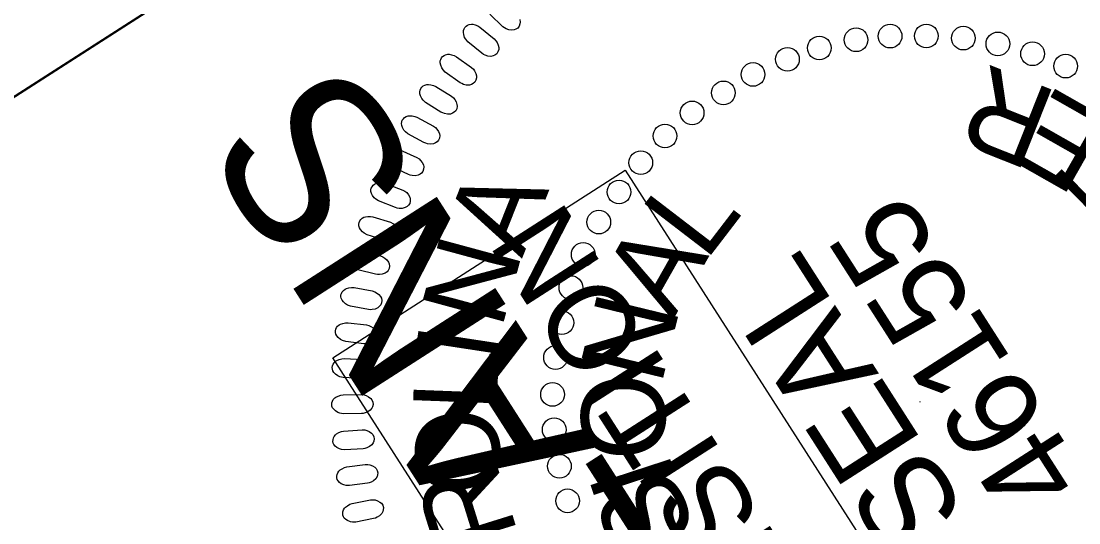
# Model space of a CAD drawing. Extents: x 476646 to 478477, y 498681 to 500689.
# Drawn here: x 476726.9 to 476798.5, y 500100.5 to 500134.4 of the extents above; entities that cross this region are included whole.
import ezdxf

# ---------------------------------------------------------------- set-up
doc = ezdxf.new("R2010")
doc.units = 0
for name, color, linetype in [('Sheet PE Seal Cell', 7, 'Continuous'), ('Sheet Plan CELL', 7, 'Continuous'), ('Sheet Sticker Incomplete CELL', 7, 'Continuous')]:
    doc.layers.add(name, color=color, linetype=linetype)

msp = doc.modelspace()

# ---------------------------------------------------------------- linework, layer by layer
at = {"layer": 'Sheet PE Seal Cell'}
msp.add_line((476787.749, 500108.701), (476787.788, 500108.726), dxfattribs=at)
msp.add_lwpolyline([(476760.68, 500134.556), (476760.706, 500134.379), (476760.698, 500134.253), (476760.635, 500134.098), (476760.548, 500133.975), (476760.417, 500133.893), (476760.309, 500133.85), (476760.149, 500133.825), (476759.944, 500133.852), (476759.767, 500133.926), (476759.651, 500133.992), (476759.546, 500134.069), (476758.649, 500134.905)], dxfattribs=at)
for points in [[(476758.12, 500132.269), (476757.17, 500133.047), (476757.025, 500133.215), (476756.949, 500133.344), (476756.89, 500133.538), (476756.866, 500133.682), (476756.876, 500133.82), (476756.911, 500133.926), (476756.967, 500134.025), (476757.053, 500134.099), (476757.152, 500134.173), (476757.264, 500134.216), (476757.409, 500134.234), (476757.508, 500134.23), (476757.667, 500134.187), (476757.843, 500134.119), (476757.981, 500134.036), (476758.958, 500133.245), (476759.074, 500133.12), (476759.153, 500132.996), (476759.22, 500132.826), (476759.257, 500132.651), (476759.257, 500132.525), (476759.205, 500132.365), (476759.125, 500132.238), (476758.999, 500132.147), (476758.895, 500132.098), (476758.736, 500132.063), (476758.53, 500132.077), (476758.348, 500132.139), (476758.229, 500132.198)], [(476756.644, 500130.284), (476755.648, 500131), (476755.492, 500131.159), (476755.409, 500131.282), (476755.336, 500131.472), (476755.304, 500131.616), (476755.305, 500131.753), (476755.334, 500131.861), (476755.383, 500131.964), (476755.465, 500132.043), (476755.559, 500132.123), (476755.668, 500132.173), (476755.811, 500132.2), (476755.91, 500132.202), (476756.071, 500132.169), (476756.252, 500132.113), (476756.394, 500132.038), (476757.419, 500131.31), (476757.543, 500131.193), (476757.63, 500131.075), (476757.707, 500130.909), (476757.755, 500130.736), (476757.764, 500130.61), (476757.72, 500130.448), (476757.649, 500130.315), (476757.529, 500130.217), (476757.428, 500130.161), (476757.273, 500130.116), (476757.065, 500130.119), (476756.88, 500130.169), (476756.757, 500130.22)], [(476755.353, 500128.292), (476754.315, 500128.945), (476754.149, 500129.093), (476754.058, 500129.211), (476753.974, 500129.397), (476753.934, 500129.538), (476753.925, 500129.675), (476753.947, 500129.785), (476753.99, 500129.891), (476754.067, 500129.975), (476754.156, 500130.06), (476754.262, 500130.117), (476754.402, 500130.152), (476754.501, 500130.161), (476754.664, 500130.138), (476754.848, 500130.093), (476754.995, 500130.027), (476756.063, 500129.365), (476756.194, 500129.255), (476756.289, 500129.143), (476756.376, 500128.983), (476756.435, 500128.813), (476756.451, 500128.689), (476756.418, 500128.524), (476756.355, 500128.387), (476756.242, 500128.281), (476756.144, 500128.219), (476755.992, 500128.164), (476755.784, 500128.154), (476755.597, 500128.192), (476755.471, 500128.236)], [(476754.198, 500126.236), (476753.12, 500126.822), (476752.946, 500126.96), (476752.848, 500127.071), (476752.752, 500127.251), (476752.702, 500127.389), (476752.686, 500127.526), (476752.701, 500127.637), (476752.737, 500127.745), (476752.808, 500127.834), (476752.892, 500127.924), (476752.994, 500127.988), (476753.132, 500128.032), (476753.23, 500128.046), (476753.394, 500128.034), (476753.58, 500128.001), (476753.731, 500127.945), (476754.838, 500127.351), (476754.977, 500127.25), (476755.078, 500127.143), (476755.175, 500126.989), (476755.244, 500126.824), (476755.268, 500126.7), (476755.246, 500126.534), (476755.192, 500126.393), (476755.086, 500126.281), (476754.992, 500126.212), (476754.843, 500126.148), (476754.637, 500126.124), (476754.447, 500126.151), (476754.319, 500126.187)], [(476753.154, 500124.067), (476752.041, 500124.584), (476751.858, 500124.711), (476751.753, 500124.817), (476751.647, 500124.99), (476751.588, 500125.125), (476751.563, 500125.26), (476751.571, 500125.372), (476751.6, 500125.482), (476751.666, 500125.575), (476751.744, 500125.671), (476751.842, 500125.74), (476751.977, 500125.793), (476752.074, 500125.814), (476752.239, 500125.812), (476752.426, 500125.79), (476752.58, 500125.744), (476753.723, 500125.221), (476753.867, 500125.129), (476753.974, 500125.029), (476754.081, 500124.88), (476754.161, 500124.72), (476754.192, 500124.598), (476754.181, 500124.431), (476754.135, 500124.287), (476754.036, 500124.168), (476753.947, 500124.094), (476753.802, 500124.021), (476753.599, 500123.984), (476753.407, 500123.999), (476753.277, 500124.026)], [(476752.272, 500121.837), (476751.13, 500122.284), (476750.939, 500122.399), (476750.828, 500122.498), (476750.71, 500122.664), (476750.644, 500122.795), (476750.61, 500122.928), (476750.611, 500123.04), (476750.633, 500123.152), (476750.693, 500123.249), (476750.764, 500123.349), (476750.858, 500123.425), (476750.989, 500123.486), (476751.085, 500123.513), (476751.249, 500123.521), (476751.438, 500123.512), (476751.594, 500123.475), (476752.768, 500123.024), (476752.917, 500122.942), (476753.032, 500122.849), (476753.147, 500122.708), (476753.236, 500122.552), (476753.275, 500122.433), (476753.274, 500122.265), (476753.238, 500122.118), (476753.147, 500121.994), (476753.062, 500121.914), (476752.923, 500121.832), (476752.722, 500121.782), (476752.53, 500121.785), (476752.398, 500121.804)], [(476751.527, 500119.624), (476750.358, 500119.998), (476750.161, 500120.101), (476750.043, 500120.193), (476749.916, 500120.351), (476749.841, 500120.478), (476749.799, 500120.609), (476749.793, 500120.72), (476749.808, 500120.834), (476749.862, 500120.934), (476749.927, 500121.039), (476750.015, 500121.121), (476750.142, 500121.19), (476750.237, 500121.222), (476750.4, 500121.241), (476750.589, 500121.243), (476750.747, 500121.216), (476751.947, 500120.84), (476752.101, 500120.767), (476752.221, 500120.682), (476752.345, 500120.548), (476752.444, 500120.398), (476752.491, 500120.281), (476752.5, 500120.114), (476752.473, 500119.965), (476752.39, 500119.835), (476752.31, 500119.751), (476752.177, 500119.66), (476751.979, 500119.598), (476751.787, 500119.588), (476751.655, 500119.599)], [(476750.927, 500117.325), (476749.738, 500117.624), (476749.534, 500117.714), (476749.411, 500117.799), (476749.274, 500117.949), (476749.192, 500118.07), (476749.142, 500118.198), (476749.128, 500118.31), (476749.136, 500118.423), (476749.184, 500118.527), (476749.242, 500118.636), (476749.325, 500118.723), (476749.447, 500118.8), (476749.54, 500118.838), (476749.701, 500118.867), (476749.889, 500118.881), (476750.05, 500118.864), (476751.27, 500118.564), (476751.429, 500118.501), (476751.554, 500118.423), (476751.686, 500118.298), (476751.794, 500118.155), (476751.848, 500118.041), (476751.868, 500117.874), (476751.851, 500117.724), (476751.776, 500117.589), (476751.702, 500117.5), (476751.574, 500117.401), (476751.38, 500117.326), (476751.189, 500117.305), (476751.056, 500117.308)], [(476750.444, 500114.942), (476749.238, 500115.167), (476749.029, 500115.243), (476748.901, 500115.32), (476748.755, 500115.461), (476748.665, 500115.577), (476748.607, 500115.702), (476748.586, 500115.812), (476748.588, 500115.926), (476748.628, 500116.032), (476748.679, 500116.144), (476748.757, 500116.237), (476748.874, 500116.321), (476748.964, 500116.366), (476749.123, 500116.404), (476749.31, 500116.43), (476749.471, 500116.423), (476750.708, 500116.201), (476750.87, 500116.147), (476750.999, 500116.078), (476751.14, 500115.96), (476751.257, 500115.825), (476751.318, 500115.715), (476751.348, 500115.549), (476751.34, 500115.399), (476751.273, 500115.259), (476751.205, 500115.166), (476751.084, 500115.059), (476750.895, 500114.972), (476750.707, 500114.939), (476750.574, 500114.933)], [(476750.126, 500112.633), (476748.908, 500112.782), (476748.695, 500112.845), (476748.563, 500112.914), (476748.408, 500113.046), (476748.311, 500113.155), (476748.245, 500113.276), (476748.218, 500113.385), (476748.212, 500113.499), (476748.245, 500113.607), (476748.29, 500113.723), (476748.361, 500113.819), (476748.473, 500113.911), (476748.559, 500113.961), (476748.716, 500114.009), (476748.902, 500114.047), (476749.063, 500114.051), (476750.311, 500113.906), (476750.477, 500113.863), (476750.61, 500113.802), (476750.757, 500113.694), (476750.883, 500113.565), (476750.95, 500113.459), (476750.991, 500113.296), (476750.992, 500113.145), (476750.935, 500113.002), (476750.872, 500112.904), (476750.758, 500112.79), (476750.576, 500112.692), (476750.388, 500112.647), (476750.256, 500112.633)], [(476749.957, 500110.274), (476748.733, 500110.345), (476748.515, 500110.395), (476748.379, 500110.456), (476748.216, 500110.578), (476748.113, 500110.681), (476748.039, 500110.797), (476748.006, 500110.905), (476747.992, 500111.018), (476748.018, 500111.128), (476748.055, 500111.246), (476748.121, 500111.347), (476748.227, 500111.446), (476748.31, 500111.501), (476748.463, 500111.559), (476748.646, 500111.608), (476748.807, 500111.622), (476750.062, 500111.556), (476750.229, 500111.523), (476750.366, 500111.47), (476750.52, 500111.372), (476750.654, 500111.252), (476750.727, 500111.15), (476750.778, 500110.99), (476750.789, 500110.839), (476750.741, 500110.692), (476750.684, 500110.591), (476750.578, 500110.47), (476750.401, 500110.361), (476750.218, 500110.304), (476750.087, 500110.281)], [(476749.965, 500107.904), (476748.739, 500107.898), (476748.519, 500107.934), (476748.379, 500107.986), (476748.209, 500108.097), (476748.099, 500108.194), (476748.019, 500108.306), (476747.978, 500108.41), (476747.958, 500108.522), (476747.977, 500108.634), (476748.007, 500108.754), (476748.066, 500108.859), (476748.165, 500108.964), (476748.245, 500109.024), (476748.394, 500109.093), (476748.573, 500109.153), (476748.733, 500109.176), (476749.989, 500109.189), (476750.159, 500109.167), (476750.299, 500109.123), (476750.459, 500109.034), (476750.599, 500108.923), (476750.68, 500108.826), (476750.74, 500108.669), (476750.76, 500108.52), (476750.721, 500108.371), (476750.671, 500108.265), (476750.573, 500108.137), (476750.404, 500108.018), (476750.224, 500107.949), (476750.095, 500107.919)], [(476750.079, 500105.531), (476748.855, 500105.448), (476748.634, 500105.471), (476748.491, 500105.514), (476748.315, 500105.614), (476748.199, 500105.704), (476748.111, 500105.811), (476748.064, 500105.912), (476748.037, 500106.023), (476748.05, 500106.136), (476748.071, 500106.257), (476748.124, 500106.366), (476748.216, 500106.477), (476748.292, 500106.542), (476748.436, 500106.619), (476748.612, 500106.691), (476748.769, 500106.724), (476750.023, 500106.816), (476750.193, 500106.805), (476750.336, 500106.77), (476750.501, 500106.691), (476750.648, 500106.588), (476750.734, 500106.497), (476750.804, 500106.344), (476750.834, 500106.197), (476750.805, 500106.045), (476750.762, 500105.937), (476750.67, 500105.803), (476750.509, 500105.673), (476750.335, 500105.594), (476750.207, 500105.555)], [(476750.371, 500103.195), (476749.155, 500103.036), (476748.933, 500103.044), (476748.788, 500103.078), (476748.605, 500103.167), (476748.483, 500103.249), (476748.39, 500103.35), (476748.337, 500103.449), (476748.302, 500103.558), (476748.308, 500103.671), (476748.322, 500103.794), (476748.367, 500103.905), (476748.453, 500104.022), (476748.524, 500104.092), (476748.664, 500104.178), (476748.834, 500104.26), (476748.989, 500104.304), (476750.234, 500104.474), (476750.405, 500104.474), (476750.55, 500104.447), (476750.72, 500104.379), (476750.873, 500104.286), (476750.964, 500104.2), (476751.044, 500104.052), (476751.083, 500103.906), (476751.063, 500103.754), (476751.027, 500103.643), (476750.945, 500103.504), (476750.792, 500103.364), (476750.623, 500103.273), (476750.498, 500103.227)], [(476750.796, 500100.805), (476749.592, 500100.569), (476749.369, 500100.564), (476749.222, 500100.588), (476749.034, 500100.666), (476748.908, 500100.74), (476748.808, 500100.835), (476748.749, 500100.93), (476748.707, 500101.036), (476748.706, 500101.15), (476748.712, 500101.273), (476748.751, 500101.387), (476748.829, 500101.509), (476748.895, 500101.583), (476749.029, 500101.678), (476749.194, 500101.771), (476749.346, 500101.824), (476750.578, 500102.072), (476750.749, 500102.082), (476750.895, 500102.065), (476751.068, 500102.008), (476751.227, 500101.925), (476751.324, 500101.845), (476751.412, 500101.702), (476751.461, 500101.559), (476751.45, 500101.405), (476751.422, 500101.292), (476751.348, 500101.148), (476751.204, 500100.999), (476751.041, 500100.898), (476750.92, 500100.844)]]:
    msp.add_lwpolyline(points, close=True, dxfattribs=at)
for centre in [(476785.739, 500133.43), (476788.192, 500133.442), (476790.698, 500133.298), (476780.952, 500132.631), (476783.437, 500133.183), (476793.033, 500132.903), (476778.794, 500131.862), (476795.381, 500132.237), (476797.619, 500131.402), (476776.467, 500130.843), (476774.461, 500129.592), (476772.348, 500128.237), (476770.508, 500126.679), (476768.873, 500124.874), (476767.4, 500122.89), (476766.032, 500120.857), (476764.976, 500118.666), (476764.14, 500116.428), (476763.533, 500114.053), (476763.103, 500111.696), (476762.903, 500109.203), (476763.014, 500106.816), (476763.367, 500104.346), (476763.921, 500102.006)]:
    msp.add_circle(centre, 0.801, dxfattribs=at)
at = {"layer": 'Sheet Plan CELL'}
for points in [[(476674.53, 500096.039), (477484.51, 498833.484), (478368.276, 499400.456), (477558.31, 500662.99)], [(476760.156, 500032.132), (476706.155, 500116.283), (476800.848, 500177.047), (476854.856, 500092.886)]]:
    msp.add_lwpolyline(points, close=True, dxfattribs=at)
at = {"layer": 'Sheet Sticker Incomplete CELL'}
msp.add_lwpolyline([(476847.189, 500000.642), (476827.409, 499987.953), (476748.033, 500111.68), (476767.813, 500124.369)], close=True, dxfattribs=at)

# ---------------------------------------------------------------- texts
at = {"layer": 'Sheet PE Seal Cell'}
for s, height, rotation, p in [('R', 5.669, 158.34537, (476797.235, 500129.598)), ('E', 5.669, 150.40558, (476801.013, 500127.53)), ('E', 5.669, 134.52598, (476804.156, 500124.71)), ('A', 5.669, 68.35464, (476760.829, 500118.366)), ('L', 5.669, 52.51267, (476773.248, 500118.145)), ('46155', 6.2363, 122.66317, (476799.071, 500103.619)), ('N', 5.669, 74.84399, (476759.44, 500113.53)), ('A', 5.669, 60.45247, (476771.033, 500114.2)), ('SEAL', 6.2363, 122.66317, (476791.003, 500101.233)), ('N', 5.669, 76.33206, (476770.242, 500109.728)), ('I', 5.669, 81.33335, (476759.22, 500111.244)), ('L', 5.669, 87.82271, (476759.114, 500107.977)), ('O', 5.669, 92.21165, (476770.631, 500104.855)), ('O', 5.669, 94.31206, (476759.539, 500102.627)), ('I', 5.669, 108.09125, (476771.298, 500103.496)), ('R', 5.669, 107.29078, (476760.585, 500099.786)), ('S', 5.669, 116.03105, (476772.818, 500099.957))]:
    msp.add_text(s, height=height, rotation=rotation, dxfattribs=at).set_placement(p)
at = {"layer": 'Sheet Sticker Incomplete CELL'}
for s, height, p in [('INCOMPLETE PLANS', 11.52, (476832.508, 500001.857)), ('DO NOT USE FOR R/W ACQUISITION', 5.76, (476836.603, 500008.346))]:
    msp.add_text(s, height=height, rotation=122.68181, dxfattribs=at).set_placement(p)

doc.saveas('drawing.dxf')
